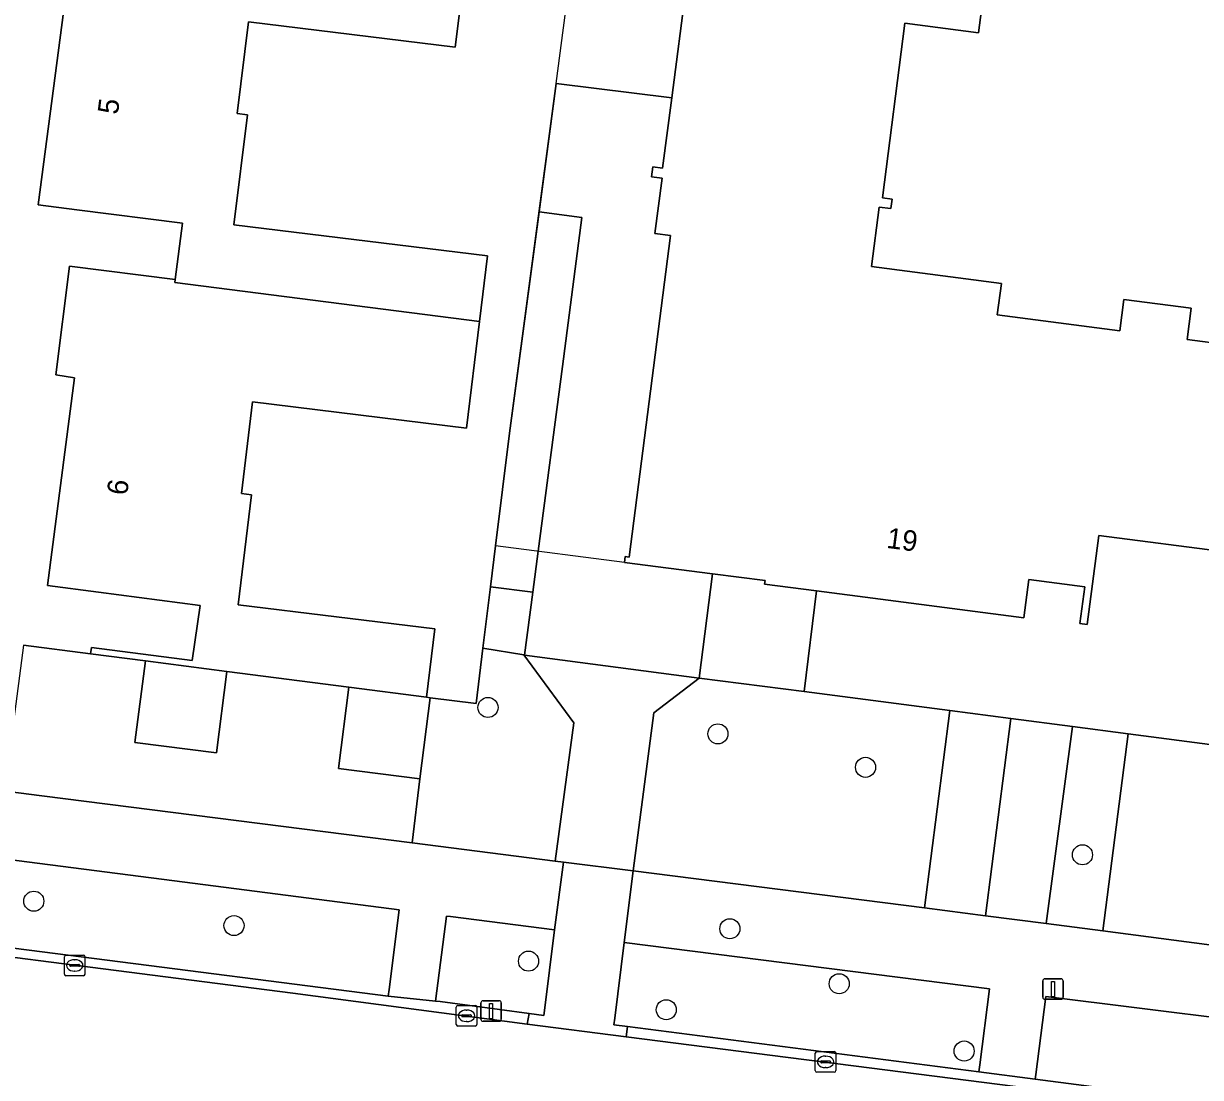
# Model space of a CAD drawing. Extents: x 162184 to 163154, y 385507 to 386516.
# Drawn here: x 162428.7 to 162486.1, y 386039.6 to 386091 of the extents above; entities that cross this region are included whole.
import ezdxf

# ---------------------------------------------------------------- set-up
doc = ezdxf.new("R2010")
doc.units = 0
for name, color, linetype in [('IMGEO_Boom', 7, 'Continuous'), ('IMGEO_Erf', 7, 'Continuous'), ('IMGEO_Groenvoorziening', 7, 'Continuous'), ('IMGEO_Hek', 7, 'Continuous'), ('IMGEO_Kolk', 7, 'Continuous'), ('IMGEO_Lichtmast', 7, 'Continuous'), ('IMGEO_Pand', 7, 'Continuous'), ('IMGEO_Pand_nummerreeks', 7, 'Continuous'), ('IMGEO_Parkeervlak_open', 7, 'Continuous'), ('IMGEO_Rijbaan_lokaal_open', 7, 'Continuous'), ('IMGEO_Voetpad_open', 7, 'Continuous')]:
    doc.layers.add(name, color=color, linetype=linetype)

msp = doc.modelspace()

# ---------------------------------------------------------------- linework, layer by layer
at = {"layer": 'IMGEO_Boom'}
for centre in [(162451.366, 386057.668), (162462.574, 386056.38), (162469.77, 386054.75), (162480.341, 386050.488), (162429.227, 386048.224), (162438.987, 386047.037), (162463.156, 386046.884), (162453.342, 386045.303), (162468.485, 386044.202), (162460.056, 386042.937), (162474.576, 386040.923)]:
    msp.add_circle(centre, 0.489, dxfattribs=at)
at = {"layer": 'IMGEO_Erf'}
for points in [[(162476.768, 386102.051), (162475.283, 386090.549), (162471.688, 386091.014), (162470.588, 386082.498), (162471.059, 386082.437), (162471, 386081.983), (162470.441, 386082.056), (162470.066, 386079.151), (162476.389, 386078.335), (162476.19, 386076.797), (162482.159, 386076.027), (162482.356, 386077.553), (162485.644, 386077.128), (162485.447, 386075.601), (162491.44, 386074.827)], [(162450.086, 386092.442), (162449.77, 386089.853), (162439.688, 386091.084), (162439.142, 386086.614), (162439.638, 386086.553), (162438.983, 386081.189), (162451.347, 386079.68), (162450.955, 386076.471), (162450.321, 386071.286), (162439.892, 386072.56), (162439.346, 386068.09), (162439.841, 386068.029), (162439.187, 386062.665), (162448.77, 386061.495), (162448.363, 386058.167), (162448.556, 386058.142), (162450.787, 386057.854), (162451.121, 386060.554), (162451.491, 386063.543), (162451.74, 386065.549), (162452.419, 386071.03), (162453.861, 386081.821), (162454.696, 386088.073), (162460.323, 386087.377), (162461.718, 386098.188)], [(162428.719, 386060.699), (162431.998, 386060.278), (162432.039, 386060.596), (162436.949, 386059.963), (162437.333, 386062.638), (162432.386, 386063.284), (162429.896, 386063.609), (162431.219, 386073.74), (162430.298, 386073.878), (162430.975, 386079.181), (162436.124, 386078.528), (162436.473, 386081.271), (162431.329, 386081.925), (162429.444, 386082.164), (162430.77, 386092.306)]]:
    msp.add_lwpolyline(points, dxfattribs=at)
msp.add_lwpolyline([(162524.4, 386070.798), (162522.905, 386071.008), (162521.5, 386061.019), (162518.132, 386061.454), (162518.109, 386061.276), (162500, 386063.614), (162481.133, 386066.05), (162480.573, 386061.707), (162480.222, 386061.752), (162480.453, 386063.545), (162477.722, 386063.898), (162477.483, 386062.04), (162467.38, 386063.345), (162466.784, 386058.45), (162473.878, 386057.522), (162476.853, 386057.133), (162479.853, 386056.74), (162482.563, 386056.386), (162495.261, 386054.726), (162500, 386054.106), (162515.064, 386052.135), (162521.578, 386051.283), (162521.727, 386051.263)], close=True, dxfattribs=at)
at = {"layer": 'IMGEO_Groenvoorziening'}
for points in [[(162448.046, 386054.19), (162444.077, 386054.687), (162444.589, 386058.654), (162438.638, 386059.421), (162438.126, 386055.454), (162434.159, 386055.966), (162434.67, 386059.933), (162431.998, 386060.278), (162428.719, 386060.699), (162428.21, 386056.731), (162424.242, 386057.239), (162424.751, 386061.206), (162416.817, 386062.224), (162415.88, 386055.128), (162429.615, 386053.363), (162447.668, 386051.07)], [(162454.648, 386050.183), (162455.557, 386056.911), (162453.108, 386060.226), (162451.121, 386060.554), (162450.787, 386057.854), (162448.556, 386058.142), (162448.046, 386054.19), (162447.668, 386051.07)], [(162434.67, 386059.933), (162434.159, 386055.966), (162438.126, 386055.454), (162438.638, 386059.421)], [(162472.641, 386047.895), (162473.878, 386057.522), (162466.784, 386058.45), (162461.659, 386059.103), (162459.455, 386057.4), (162458.436, 386049.702)], [(162448.046, 386054.19), (162448.556, 386058.142), (162448.363, 386058.167), (162444.589, 386058.654), (162444.077, 386054.687)], [(162475.618, 386047.518), (162476.853, 386057.133), (162473.878, 386057.522), (162472.641, 386047.895)], [(162482.563, 386056.386), (162479.853, 386056.74), (162478.571, 386047.142), (162481.339, 386046.773)], [(162520.412, 386041.654), (162521.727, 386051.263), (162521.578, 386051.283), (162515.064, 386052.135), (162500, 386054.106), (162495.261, 386054.726), (162482.563, 386056.386), (162481.339, 386046.773), (162500, 386044.328)], [(162436.597, 386049.145), (162421.308, 386051.115), (162417.099, 386051.668), (162416.565, 386047.431), (162446.5, 386043.591), (162446.543, 386043.929), (162447.038, 386047.8)], [(162454.616, 386046.823), (162449.544, 386047.477), (162449.337, 386047.503), (162448.803, 386043.361), (162449.031, 386043.331), (162453.368, 386042.756), (162454.094, 386042.659), (162454.126, 386042.899)], [(162475.809, 386043.954), (162458.011, 386046.211), (162457.543, 386042.52), (162457.503, 386042.203), (162458.164, 386042.118), (162475.292, 386039.909), (162475.336, 386040.252)], [(162478.556, 386043.58), (162478.063, 386039.785), (162478.033, 386039.554), (162487.53, 386038.32), (162498.29, 386036.923), (162500.92, 386036.604), (162519.499, 386034.169), (162519.545, 386034.527), (162520.029, 386038.411)]]:
    msp.add_lwpolyline(points, close=True, dxfattribs=at)
at = {"layer": 'IMGEO_Hek'}
for points in [[(162454.696, 386088.073), (162457.574, 386110.037)], [(162452.419, 386071.03), (162454.696, 386088.073)], [(162454.696, 386088.073), (162460.323, 386087.377)], [(162458.017, 386064.739), (162451.74, 386065.549)]]:
    msp.add_lwpolyline(points, dxfattribs=at)
at = {"layer": 'IMGEO_Kolk'}
for p, q in [((162430.723, 386044.669), (162430.723, 386045.521)), ((162430.798, 386045.595), (162431.65, 386045.595)), ((162431.211, 386045.375), (162431.236, 386045.375)), ((162431.724, 386045.521), (162431.724, 386044.669)), ((162430.982, 386045.089), (162430.982, 386045.101)), ((162431.42, 386045.052), (162431.022, 386045.052)), ((162431.025, 386045.138), (162431.423, 386045.138)), ((162431.234, 386044.815), (162431.209, 386044.815)), ((162431.466, 386045.101), (162431.466, 386045.089)), ((162431.65, 386044.595), (162430.798, 386044.595)), ((162449.822, 386042.214), (162449.822, 386043.066)), ((162449.897, 386043.14), (162450.749, 386043.14)), ((162450.823, 386043.066), (162450.823, 386042.214)), ((162450.081, 386042.634), (162450.081, 386042.646)), ((162450.519, 386042.597), (162450.121, 386042.597)), ((162450.124, 386042.683), (162450.522, 386042.683)), ((162450.31, 386042.92), (162450.335, 386042.92)), ((162450.565, 386042.646), (162450.565, 386042.634)), ((162450.749, 386042.14), (162449.897, 386042.14)), ((162450.333, 386042.36), (162450.308, 386042.36)), ((162467.32, 386039.968), (162467.32, 386040.82)), ((162467.395, 386040.894), (162468.247, 386040.894)), ((162468.321, 386040.82), (162468.321, 386039.968)), ((162467.579, 386040.388), (162467.579, 386040.4)), ((162468.017, 386040.351), (162467.619, 386040.351)), ((162467.622, 386040.437), (162468.02, 386040.437)), ((162467.808, 386040.674), (162467.833, 386040.674)), ((162468.063, 386040.4), (162468.063, 386040.388)), ((162468.247, 386039.894), (162467.395, 386039.894)), ((162467.831, 386040.114), (162467.806, 386040.114))]:
    msp.add_line(p, q, dxfattribs=at)
for points in [[(162430.723, 386044.669), (162430.723, 386045.521)], [(162430.798, 386045.595), (162431.65, 386045.595)], [(162431.724, 386045.521), (162431.724, 386044.669)], [(162431.65, 386044.595), (162430.798, 386044.595)], [(162449.822, 386042.214), (162449.822, 386043.066)], [(162449.897, 386043.14), (162450.749, 386043.14)], [(162450.823, 386043.066), (162450.823, 386042.214)], [(162450.749, 386042.14), (162449.897, 386042.14)], [(162467.32, 386039.968), (162467.32, 386040.82)], [(162467.395, 386040.894), (162468.247, 386040.894)], [(162468.321, 386040.82), (162468.321, 386039.968)], [(162468.247, 386039.894), (162467.395, 386039.894)]]:
    msp.add_lwpolyline(points, dxfattribs=at)
for centre, radius, start, end in [((162430.8, 386045.519), 0.0765, 91.55205, 178.44795), ((162430.8, 386045.519), 0.0765, 91.55205, 178.44795), ((162431.648, 386045.519), 0.0765, 1.55205, 88.44795), ((162431.648, 386045.519), 0.0765, 1.55205, 88.44795), ((162431.022, 386045.098), 0.0403, 85.87752, 175.75265), ((162431.019, 386045.088), 0.0366, 178.93798, 274.71019), ((162431.423, 386045.095), 0.043, 264.86636, 352.45326), ((162431.427, 386045.1), 0.0386, 1.73085, 96.63898), ((162430.8, 386044.671), 0.0765, 181.55205, 268.44795), ((162430.8, 386044.671), 0.0765, 181.55205, 268.44795), ((162431.648, 386044.671), 0.0765, 271.55205, 358.44795), ((162431.648, 386044.671), 0.0765, 271.55205, 358.44795), ((162449.899, 386043.064), 0.0765, 91.55205, 178.44795), ((162449.899, 386043.064), 0.0765, 91.55205, 178.44795), ((162450.747, 386043.064), 0.0765, 1.55205, 88.44795), ((162450.747, 386043.064), 0.0765, 1.55205, 88.44795), ((162450.121, 386042.643), 0.0403, 85.87752, 175.75265), ((162450.118, 386042.633), 0.0366, 178.93798, 274.71019), ((162450.522, 386042.64), 0.043, 264.86636, 352.45326), ((162450.526, 386042.645), 0.0386, 1.73085, 96.63898), ((162449.899, 386042.216), 0.0765, 181.55205, 268.44795), ((162449.899, 386042.216), 0.0765, 181.55205, 268.44795), ((162450.747, 386042.216), 0.0765, 271.55205, 358.44795), ((162450.747, 386042.216), 0.0765, 271.55205, 358.44795), ((162467.397, 386040.818), 0.0765, 91.55205, 178.44795), ((162467.397, 386040.818), 0.0765, 91.55205, 178.44795), ((162468.245, 386040.818), 0.0765, 1.55205, 88.44795), ((162468.245, 386040.818), 0.0765, 1.55205, 88.44795), ((162467.619, 386040.397), 0.0403, 85.87752, 175.75265), ((162467.616, 386040.387), 0.0366, 178.93798, 274.71019), ((162468.02, 386040.394), 0.043, 264.86636, 352.45326), ((162468.024, 386040.399), 0.0386, 1.73085, 96.63898), ((162467.397, 386039.97), 0.0765, 181.55205, 268.44795), ((162467.397, 386039.97), 0.0765, 181.55205, 268.44795), ((162468.245, 386039.97), 0.0765, 271.55205, 358.44795), ((162468.245, 386039.97), 0.0765, 271.55205, 358.44795)]:
    msp.add_arc(centre, radius, start, end, dxfattribs=at)
for centre, major_axis, ratio, start_param, end_param in [((162431.21, 386045.095), (-0.387, 0.002), 0.722429, 4.712389, 7.853982), ((162431.235, 386045.095), (-0.39, 0.002), 0.717154, 1.570796, 4.712389), ((162450.309, 386042.64), (-0.387, 0.002), 0.722429, 4.712389, 7.853982), ((162450.334, 386042.64), (-0.39, 0.002), 0.717154, 1.570796, 4.712389), ((162467.807, 386040.394), (-0.387, 0.002), 0.722429, 4.712389, 7.853982), ((162467.832, 386040.394), (-0.39, 0.002), 0.717154, 1.570796, 4.712389)]:
    msp.add_ellipse(centre, major_axis=major_axis, ratio=ratio, start_param=start_param, end_param=end_param, dxfattribs=at)
at = {"layer": 'IMGEO_Lichtmast'}
for p, q in [((162478.41, 386043.544), (162478.41, 386044.344)), ((162478.41, 386044.344), (162478.41, 386043.544)), ((162478.51, 386044.444), (162479.3, 386044.444)), ((162479.3, 386044.444), (162478.51, 386044.444)), ((162479.4, 386044.344), (162479.4, 386043.544)), ((162479.4, 386043.544), (162479.4, 386044.344)), ((162451.024, 386042.472), (162451.024, 386043.272)), ((162451.024, 386043.272), (162451.024, 386042.472)), ((162451.124, 386043.372), (162451.914, 386043.372)), ((162451.914, 386043.372), (162451.124, 386043.372)), ((162452.014, 386043.272), (162452.014, 386042.472)), ((162452.014, 386042.472), (162452.014, 386043.272)), ((162479.3, 386043.444), (162478.51, 386043.444)), ((162478.51, 386043.444), (162479.3, 386043.444)), ((162451.914, 386042.372), (162451.124, 386042.372)), ((162451.124, 386042.372), (162451.914, 386042.372))]:
    msp.add_line(p, q, dxfattribs=at)
for points in [[(162478.83, 386044.319), (162478.98, 386044.319), (162478.98, 386043.569), (162478.83, 386043.569), (162478.83, 386044.319)], [(162451.444, 386043.247), (162451.594, 386043.247), (162451.594, 386042.497), (162451.444, 386042.497), (162451.444, 386043.247)]]:
    msp.add_lwpolyline(points, dxfattribs=at)
for centre, start, end in [((162478.51, 386044.344), 90, 180), ((162478.51, 386044.344), 90, 180), ((162479.3, 386044.344), 0, 90), ((162479.3, 386044.344), 360, 90), ((162451.124, 386043.272), 90, 180), ((162451.124, 386043.272), 90, 180), ((162451.914, 386043.272), 0, 90), ((162451.914, 386043.272), 360, 90), ((162478.51, 386043.544), 180, 270), ((162478.51, 386043.544), 180, 270), ((162479.3, 386043.544), 270, 0), ((162479.3, 386043.544), 270, 0), ((162451.124, 386042.472), 180, 270), ((162451.124, 386042.472), 180, 270), ((162451.914, 386042.472), 270, 0), ((162451.914, 386042.472), 270, 0)]:
    msp.add_arc(centre, 0.1, start, end, dxfattribs=at)
at = {"layer": 'IMGEO_Pand'}
for points in [[(162491.44, 386074.827), (162485.447, 386075.601), (162485.644, 386077.128), (162482.356, 386077.553), (162482.159, 386076.027), (162476.19, 386076.797), (162476.389, 386078.335), (162470.066, 386079.151), (162470.441, 386082.056), (162471, 386081.983), (162471.059, 386082.437), (162470.588, 386082.498), (162471.688, 386091.014), (162475.283, 386090.549), (162476.768, 386102.051)], [(162461.718, 386098.188), (162460.323, 386087.377), (162459.88, 386083.949), (162459.401, 386084.01), (162459.339, 386083.527), (162459.853, 386083.461), (162459.505, 386080.763), (162460.265, 386080.665), (162458.242, 386064.996), (162458.053, 386065.02), (162458.017, 386064.739), (162462.315, 386064.184), (162464.875, 386063.854), (162464.852, 386063.671), (162467.38, 386063.345), (162477.483, 386062.04), (162477.722, 386063.898), (162480.453, 386063.545), (162480.222, 386061.752), (162480.573, 386061.707), (162481.133, 386066.05), (162500, 386063.614)]]:
    msp.add_lwpolyline(points, dxfattribs=at)
for points in [[(162450.086, 386092.442), (162450.404, 386095.045), (162436.186, 386096.848), (162436.208, 386097.025), (162431.348, 386097.618), (162430.532, 386097.717), (162429.857, 386092.423), (162430.77, 386092.306), (162429.444, 386082.164), (162431.329, 386081.925), (162436.473, 386081.271), (162436.124, 386078.528), (162436.104, 386078.372), (162450.955, 386076.471), (162451.347, 386079.68), (162438.983, 386081.189), (162439.638, 386086.553), (162439.142, 386086.614), (162439.688, 386091.084), (162449.77, 386089.853)], [(162438.638, 386059.421), (162444.589, 386058.654), (162448.363, 386058.167), (162448.77, 386061.495), (162439.187, 386062.665), (162439.841, 386068.029), (162439.346, 386068.09), (162439.892, 386072.56), (162450.321, 386071.286), (162450.955, 386076.471), (162436.104, 386078.372), (162436.124, 386078.528), (162430.975, 386079.181), (162430.298, 386073.878), (162431.219, 386073.74), (162429.896, 386063.609), (162432.386, 386063.284), (162437.333, 386062.638), (162436.949, 386059.963), (162432.039, 386060.596), (162431.998, 386060.278), (162434.67, 386059.933)]]:
    msp.add_lwpolyline(points, close=True, dxfattribs=at)
at = {"layer": 'IMGEO_Parkeervlak_open'}
for points in [[(162454.992, 386074.289), (162455.945, 386081.543), (162453.861, 386081.821), (162452.419, 386071.03), (162451.74, 386065.549), (162451.491, 386063.543), (162453.547, 386063.289), (162453.809, 386065.282)], [(162467.38, 386063.345), (162464.852, 386063.671), (162464.875, 386063.854), (162462.315, 386064.184), (162461.659, 386059.103), (162466.784, 386058.45)]]:
    msp.add_lwpolyline(points, close=True, dxfattribs=at)
at = {"layer": 'IMGEO_Rijbaan_lokaal_open'}
msp.add_lwpolyline([(162460.265, 386080.665), (162459.505, 386080.763), (162459.853, 386083.461), (162459.339, 386083.527), (162459.401, 386084.01), (162459.88, 386083.949), (162460.323, 386087.377), (162454.696, 386088.073), (162453.861, 386081.821), (162455.945, 386081.543), (162454.992, 386074.289), (162453.809, 386065.282), (162453.547, 386063.289), (162453.145, 386060.221), (162461.659, 386059.103), (162462.315, 386064.184), (162458.017, 386064.739), (162458.053, 386065.02), (162458.242, 386064.996)], close=True, dxfattribs=at)
msp.add_lwpolyline([(162500, 386036.267), (162458.097, 386041.609), (162453.274, 386042.224), (162441.857, 386043.741), (162416.511, 386047), (162403.455, 386048.678), (162392.654, 386050.067), (162370.437, 386052.921), (162333.146, 386057.71), (162331.957, 386057.856)], dxfattribs=at)
at = {"layer": 'IMGEO_Voetpad_open'}
for points in [[(162453.547, 386063.289), (162451.491, 386063.543), (162451.121, 386060.554), (162453.108, 386060.226), (162453.145, 386060.221)], [(162459.455, 386057.4), (162461.659, 386059.103), (162453.145, 386060.221), (162453.108, 386060.226), (162455.557, 386056.911), (162454.648, 386050.183), (162455.042, 386050.133), (162458.436, 386049.702)], [(162479.853, 386056.74), (162476.853, 386057.133), (162475.618, 386047.518), (162478.571, 386047.142)], [(162458.011, 386046.211), (162458.436, 386049.702), (162455.042, 386050.133), (162454.616, 386046.823), (162454.126, 386042.899), (162454.094, 386042.659), (162453.368, 386042.756), (162453.274, 386042.224), (162458.097, 386041.609), (162458.164, 386042.118), (162457.503, 386042.203), (162457.543, 386042.52)], [(162446.5, 386043.591), (162416.565, 386047.431), (162416.511, 386047), (162441.857, 386043.741), (162453.274, 386042.224), (162453.368, 386042.756), (162449.031, 386043.331), (162448.803, 386043.361)], [(162500.92, 386036.604), (162498.29, 386036.923), (162487.53, 386038.32), (162478.033, 386039.554), (162475.292, 386039.909), (162458.164, 386042.118), (162458.097, 386041.609), (162500, 386036.267), (162530.454, 386032.366), (162531.037, 386032.79), (162525.455, 386033.429), (162521.616, 386033.939), (162519.499, 386034.169)]]:
    msp.add_lwpolyline(points, close=True, dxfattribs=at)
for points in [[(162421.308, 386051.115), (162436.597, 386049.145), (162447.038, 386047.8), (162446.543, 386043.929), (162446.5, 386043.591), (162448.803, 386043.361), (162449.337, 386047.503), (162449.544, 386047.477), (162454.616, 386046.823), (162455.042, 386050.133), (162454.648, 386050.183), (162447.668, 386051.07), (162429.615, 386053.363), (162415.88, 386055.128)], [(162522.542, 386041.382), (162520.412, 386041.654), (162500, 386044.328), (162481.339, 386046.773), (162478.571, 386047.142), (162475.618, 386047.518), (162472.641, 386047.895), (162458.436, 386049.702), (162458.011, 386046.211), (162475.809, 386043.954), (162475.336, 386040.252), (162475.292, 386039.909), (162478.033, 386039.554), (162478.063, 386039.785), (162478.556, 386043.58), (162520.029, 386038.411), (162519.545, 386034.527), (162519.499, 386034.169), (162521.616, 386033.939), (162521.653, 386034.242), (162522.13, 386038.154), (162531.826, 386036.993)]]:
    msp.add_lwpolyline(points, dxfattribs=at)

# ---------------------------------------------------------------- texts
at = {"layer": 'IMGEO_Pand_nummerreeks'}
for s, rotation, p in [('5', 82.55176, (162433.324, 386086.537)), ('6', 82.55989, (162433.774, 386067.977)), ('19', 352.64322, (162470.761, 386065.449))]:
    msp.add_text(s, height=1, rotation=rotation, dxfattribs=at).set_placement(p)

doc.saveas('drawing.dxf')
